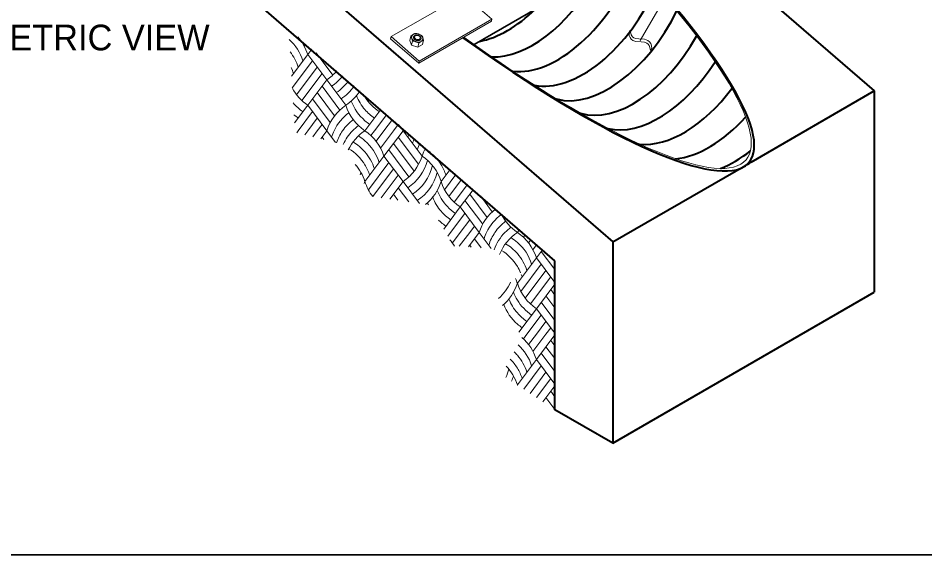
# Model space of a CAD drawing. Extents: x 99860 to 103153, y 99998 to 102077.
# Drawn here: x 101841 to 102547, y 100000 to 100418 of the extents above; entities that cross this region are included whole.
import ezdxf
from ezdxf.enums import TextEntityAlignment as Align

# ---------------------------------------------------------------- set-up
doc = ezdxf.new("R2010")
doc.units = 0
doc.header["$LTSCALE"] = 6.4
for name, color, linetype, lineweight in [('1', 7, 'Continuous', 13), ('15', 7, 'Continuous', 13), ('20', 7, 'Continuous', 13), ('30', 7, 'Continuous', 40), ('9', 7, 'Continuous', 13)]:
    doc.layers.add(name, color=color, linetype=linetype, lineweight=lineweight)

msp = doc.modelspace()

# ---------------------------------------------------------------- linework, layer by layer
at = {"layer": '1', "lineweight": 40}
for p, q in [((101553.775, 100893.223), (102304.358, 100243.197)), ((102259.104, 100228.525), (101542.799, 100848.864)), ((101988.262, 100810.884), (102508.005, 100360.773)), ((102412.037, 100305.365), (102508.005, 100360.773)), ((102508.005, 100360.773), (102508.005, 100204.005)), ((102304.358, 100243.197), (102400.327, 100298.604)), ((102304.358, 100243.197), (102304.358, 100086.43)), ((102304.358, 100086.43), (102508.005, 100204.005))]:
    msp.add_line(p, q, dxfattribs=at)
at = {"layer": '1', "lineweight": 35}
msp.add_line((102296.76, 100455.017), (102196.139, 100396.923), dxfattribs=at)
at = {"layer": '1'}
for p, q in [((102209.658, 100415.026), (102153.09, 100382.366)), ((102210.087, 100416.759), (102153.518, 100384.099)), ((102209.658, 100415.026), (102210.087, 100416.759)), ((102131.567, 100403.11), (102131.138, 100401.377)), ((102153.09, 100382.366), (102131.138, 100401.377)), ((102153.518, 100384.099), (102131.567, 100403.11)), ((102153.09, 100382.366), (102187.598, 100402.29)), ((102153.09, 100382.366), (102153.518, 100384.099))]:
    msp.add_line(p, q, dxfattribs=at)
at = {"layer": '1', "lineweight": 35}
msp.add_lwpolyline([(99862, 99999.5), (103151, 99999.5), (103151, 102075.5), (99862, 102075.5)], close=True, dxfattribs=at)
at = {"layer": '1'}
msp.add_lwpolyline([(102210.087, 100416.759), (102188.135, 100435.77), (102131.567, 100403.11)], dxfattribs=at)
at = {"layer": '1', "lineweight": 40}
msp.add_lwpolyline([(102304.358, 100086.43), (102259.104, 100112.558), (102259.104, 100228.525)], dxfattribs=at)
for centre, major_axis, ratio, start_param, end_param in [((102135.042, 100536.619), (275.44, -231.358), 0.205372, 5.0720591, 7.3453233), ((102406.182, 100380.076), (-48, -83.138), 0.57735, 0.6990402, 0.8717561)]:
    msp.add_ellipse(centre, major_axis=major_axis, ratio=ratio, start_param=start_param, end_param=end_param, dxfattribs=at)
at = {"layer": '1'}
msp.add_ellipse((102135.042, 100536.619), major_axis=(273.144, -229.43), ratio=0.205372, start_param=5.0759591, end_param=7.3414234, dxfattribs=at)
at = {"layer": '15'}
msp.add_line((102325.738, 100400.113), (102401.808, 100531.871), dxfattribs=at)
at = {"layer": '20'}
for p, q in [((102060.461, 100400.861), (102060.714, 100401.199)), ((102063.904, 100395.553), (102065.206, 100397.289)), ((102066.579, 100389.219), (102069.698, 100393.379)), ((102073.112, 100390.408), (102086.082, 100373.114)), ((102053.988, 100372.432), (102066.579, 100389.219)), ((102054.553, 100363.286), (102070.291, 100384.27)), ((102066.579, 100389.219), (102081.428, 100369.421)), ((102057.847, 100357.779), (102074.003, 100379.32)), ((102061.924, 100353.315), (102077.716, 100374.37)), ((102066.579, 100349.622), (102081.428, 100369.421)), ((102081.428, 100369.421), (102096.277, 100349.622)), ((102077.716, 100364.471), (102091.623, 100345.928)), ((102074.003, 100359.521), (102087.546, 100341.464)), ((102056.247, 100335.846), (102066.579, 100349.622)), ((102066.579, 100349.622), (102081.428, 100329.823)), ((102070.291, 100354.571), (102084.102, 100336.156)), ((102059.154, 100329.823), (102070.291, 100344.672)), ((102111.125, 100329.823), (102123.604, 100346.461)), ((102118.55, 100329.823), (102128.096, 100342.551)), ((102066.579, 100329.823), (102074.003, 100339.722)), ((102074.003, 100329.823), (102077.716, 100334.772)), ((102125.975, 100329.823), (102132.588, 100338.641)), ((102133.399, 100329.823), (102137.081, 100334.731)), ((102137.259, 100334.576), (102140.824, 100329.823)), ((102057.956, 100328.225), (102059.154, 100329.823)), ((102064.208, 100326.662), (102066.579, 100329.823)), ((102070.46, 100325.099), (102074.003, 100329.823)), ((102076.713, 100323.535), (102081.428, 100329.822)), ((102081.428, 100329.822), (102088.319, 100320.634)), ((102115.78, 100326.129), (102118.55, 100329.823)), ((102119.857, 100321.665), (102125.975, 100329.823)), ((102123.3, 100316.357), (102133.399, 100329.823)), ((102125.975, 100310.023), (102140.824, 100329.822)), ((102140.824, 100329.822), (102155.673, 100310.023)), ((102077.716, 100324.873), (102079.181, 100322.918)), ((102133.399, 100319.923), (102149.555, 100298.382)), ((102137.112, 100324.873), (102152.999, 100303.69)), ((102129.687, 100314.973), (102145.478, 100293.918)), ((102111.125, 100290.225), (102125.975, 100310.023)), ((102125.975, 100310.023), (102140.824, 100290.225)), ((102113.8, 100283.891), (102129.687, 100305.074)), ((102117.243, 100278.583), (102133.399, 100300.124)), ((102170.521, 100290.225), (102177.51, 100299.542)), ((102123.916, 100277.58), (102137.112, 100295.174)), ((102173.196, 100283.891), (102182.002, 100295.632)), ((102176.639, 100278.583), (102186.494, 100291.723)), ((102130.595, 100276.585), (102140.824, 100290.225)), ((102137.112, 100285.275), (102145.268, 100274.4)), ((102140.824, 100290.225), (102153.626, 100273.155)), ((102180.716, 100274.119), (102190.986, 100287.813)), ((102133.399, 100280.325), (102136.909, 100275.645)), ((102185.371, 100270.426), (102195.479, 100283.903)), ((102192.795, 100280.325), (102206.338, 100262.268)), ((102201.406, 100278.744), (102210.415, 100266.732)), ((102172.501, 100253.266), (102185.371, 100270.426)), ((102185.371, 100270.426), (102200.22, 100250.627)), ((102189.083, 100275.375), (102202.894, 100256.96)), ((102177.946, 100250.627), (102189.083, 100265.476)), ((102185.371, 100250.627), (102192.795, 100260.526)), ((102175.683, 100247.609), (102177.946, 100250.627)), ((102179.253, 100242.469), (102185.371, 100250.627)), ((102184.678, 100239.803), (102192.795, 100250.627)), ((102191.76, 100239.346), (102200.22, 100250.626)), ((102192.795, 100250.627), (102196.508, 100255.576)), ((102200.22, 100250.626), (102209.54, 100238.199)), ((102229.917, 100250.627), (102231.415, 100252.624)), ((102234.572, 100246.933), (102235.908, 100248.714)), ((102196.508, 100245.677), (102201.738, 100238.702)), ((102238.649, 100242.469), (102240.4, 100244.804)), ((102192.795, 100240.727), (102193.936, 100239.206)), ((102242.092, 100237.161), (102244.892, 100240.894)), ((102244.767, 100230.827), (102249.384, 100236.984)), ((102248.479, 100235.777), (102259.104, 100221.611)), ((102229.917, 100211.029), (102244.767, 100230.827)), ((102244.767, 100230.827), (102259.104, 100211.712)), ((102232.592, 100204.695), (102248.479, 100225.878)), ((102236.035, 100199.387), (102252.191, 100220.928)), ((102240.112, 100194.923), (102255.904, 100215.978)), ((102244.767, 100191.23), (102259.104, 100210.345)), ((102252.191, 100201.129), (102259.104, 100191.913)), ((102255.904, 100206.079), (102259.104, 100201.812)), ((102248.479, 100196.179), (102259.104, 100182.013)), ((102230.985, 100172.854), (102244.767, 100191.23)), ((102237.342, 100171.431), (102248.479, 100186.28)), ((102244.767, 100191.23), (102259.104, 100172.114)), ((102244.767, 100171.431), (102252.191, 100181.33)), ((102234.572, 100167.737), (102237.342, 100171.431)), ((102238.649, 100163.273), (102244.767, 100171.431)), ((102242.092, 100157.965), (102252.191, 100171.431)), ((102252.191, 100171.431), (102255.904, 100176.38)), ((102244.767, 100151.631), (102259.104, 100170.747)), ((102255.904, 100166.481), (102259.104, 100162.214)), ((102252.191, 100161.531), (102259.104, 100152.315)), ((102229.917, 100131.833), (102244.767, 100151.631)), ((102244.767, 100151.631), (102259.104, 100132.516)), ((102248.479, 100156.581), (102259.104, 100142.415)), ((102234.833, 100128.487), (102248.479, 100146.682)), ((102239.808, 100125.222), (102252.191, 100141.732)), ((102244.784, 100121.956), (102255.904, 100136.782)), ((102249.759, 100118.69), (102259.104, 100131.149)), ((102252.191, 100121.933), (102259.104, 100112.717)), ((102255.904, 100126.883), (102259.104, 100122.616))]:
    msp.add_line(p, q, dxfattribs=at)
msp.add_lwpolyline([(102319.597, 100403.062), (102318.725, 100404.459), (102317.742, 100408.022), (102316.685, 100406.191), (102317.046, 100404.075), (102317.691, 100402.417), (102318.648, 100401.115), (102319.974, 100400.111), (102322.272, 100399.217), (102326.354, 100398.953), (102328.895, 100398.727), (102330.708, 100398.095), (102331.757, 100397.273), (102332.563, 100396.176), (102333.183, 100394.555), (102333.7, 100392.186), (102334.757, 100394.016), (102334.502, 100395.989), (102333.869, 100397.665), (102332.852, 100399.035), (102331.453, 100400.106), (102328.896, 100401.035), (102324.5, 100401.408), (102322.085, 100401.612), (102320.681, 100402.143)], close=True, dxfattribs=at)
for centre, start, end in [((102030.769, 100377.83), 56.09546, 56.09634), ((102030.769, 100377.83), 56.09229, 56.09546), ((102027.056, 100372.88), 17.6434, 47.92144), ((102030.769, 100377.83), 17.6434, 41.83649), ((102023.344, 100367.931), 17.6434, 38.31474), ((102019.632, 100362.981), 17.6434, 25.40054), ((102060.467, 100400.609), 303.90361, 319.88998), ((102064.18, 100395.659), 303.90361, 321.8678), ((102087.539, 100380.81), 208.72411, 236.09639), ((102067.892, 100390.709), 303.90361, 323.8491), ((102071.604, 100385.76), 303.90361, 325.83627), ((102075.317, 100380.81), 303.90361, 327.83179), ((102139.512, 100370.91), 201.43438, 220.94161), ((102143.224, 100375.86), 207.86013, 211.33197), ((102143.223, 100375.86), 211.33188, 236.09639), ((102083.827, 100375.86), 220.57668, 236.09639), ((102117.238, 100318.433), 123.90361, 162.3566), ((102132.087, 100361.011), 197.6434, 236.09639), ((102135.799, 100365.961), 200.24322, 228.95992), ((102080.115, 100370.91), 229.78728, 236.09639), ((102120.95, 100313.483), 126.30626, 154.22661), ((102139.511, 100370.91), 220.94154, 236.09639), ((102124.662, 100308.534), 127.1006, 145.49109), ((102128.375, 100303.584), 126.331, 135.71278), ((102135.798, 100365.961), 228.95986, 236.09639), ((102120.95, 100313.483), 154.22654, 162.3566), ((102124.662, 100308.534), 145.49102, 161.50024), ((102128.375, 100303.584), 135.71269, 155.49774), ((102132.087, 100298.634), 123.90361, 154.373), ((102090.165, 100298.634), 17.6434, 56.09634), ((102176.634, 100318.433), 160.30383, 162.3566), ((102180.346, 100313.483), 158.19633, 162.3566), ((102082.741, 100288.735), 40.94134, 59.30215), ((102086.453, 100293.684), 48.95968, 58.54646), ((102086.452, 100293.684), 17.6434, 48.95974), ((102184.058, 100308.534), 156.1156, 162.3566), ((102187.771, 100303.584), 154.05795, 162.3566), ((102079.029, 100283.785), 31.33163, 58.48736), ((102082.74, 100288.735), 17.6434, 40.94141), ((102191.483, 100298.634), 152.02004, 162.3566), ((102138.425, 100283.785), 51.29644, 58.48736), ((102119.863, 100321.413), 303.90361, 342.3566), ((102123.576, 100316.463), 303.90361, 345.01126), ((102134.713, 100278.835), 17.6434, 56.09639), ((102138.425, 100283.785), 31.33163, 46.63234), ((102075.317, 100278.835), 17.6434, 41.28523), ((102067.892, 100311.513), 345.51092, 346.31988), ((102079.028, 100283.785), 17.6434, 31.33172), ((102127.288, 100311.513), 303.90361, 346.31988), ((102138.424, 100283.785), 17.6434, 31.33172), ((102071.604, 100306.564), 342.67112, 345.77134), ((102131, 100306.564), 303.90361, 345.77133), ((102075.317, 100301.614), 339.97622, 342.3566), ((102146.935, 100301.614), 197.64354, 217.81866), ((102134.713, 100301.614), 309.08024, 342.3566), ((102206.331, 100301.614), 197.64354, 236.09639), ((102198.908, 100291.714), 201.43438, 220.94161), ((102202.62, 100296.664), 200.87781, 211.33197), ((102202.619, 100296.664), 211.33188, 236.09639), ((102195.195, 100286.765), 200.24322, 202.94034), ((102198.907, 100291.714), 220.94154, 236.09639), ((102236.03, 100239.237), 128.12233, 162.3566), ((102239.742, 100234.287), 126.30626, 154.22661), ((102250.879, 100281.815), 206.78548, 236.09639), ((102195.195, 100286.765), 224.90332, 228.95992), ((102195.194, 100286.765), 228.95986, 236.09639), ((102243.454, 100229.338), 127.1006, 145.49109), ((102239.742, 100234.287), 154.22654, 162.3566), ((102243.454, 100229.338), 145.49102, 162.3566), ((102247.167, 100224.388), 135.71269, 160.14729), ((102250.879, 100219.438), 123.90361, 158.03778), ((102247.167, 100224.388), 126.331, 135.71278), ((102208.957, 100219.438), 17.6434, 56.09634), ((102149.561, 100219.438), 33.2494, 42.59671), ((102201.533, 100209.539), 40.94134, 59.30215), ((102205.245, 100214.488), 48.95968, 58.54646), ((102205.244, 100214.488), 17.6434, 48.95974), ((102197.821, 100204.589), 31.33163, 58.48736), ((102201.532, 100209.539), 17.6434, 40.94141), ((102197.82, 100204.589), 22.93575, 31.33172), ((102194.109, 100199.639), 17.6434, 23.58804), ((102197.82, 100204.589), 17.6434, 20.65552), ((102190.396, 100227.368), 311.32441, 335.66285), ((102194.109, 100222.418), 310.33908, 342.3566), ((102265.727, 100222.418), 197.64354, 236.09639), ((102262.016, 100217.468), 200.87781, 211.33197), ((102254.591, 100207.569), 200.24322, 228.95992), ((102258.304, 100212.518), 201.43438, 220.94161), ((102262.015, 100217.468), 211.33188, 236.09639), ((102258.303, 100212.518), 220.94154, 236.09639), ((102254.59, 100207.569), 228.95986, 236.09639), ((102208.957, 100140.242), 17.6434, 49.3061), ((102201.533, 100130.343), 40.94134, 46.36292), ((102205.244, 100135.292), 17.6434, 47.71239), ((102197.821, 100125.393), 31.33163, 45.00368), ((102201.532, 100130.343), 17.6434, 40.94141), ((102186.684, 100153.121), 335.63908, 346.31988), ((102194.109, 100120.443), 17.6434, 43.63506), ((102197.82, 100125.393), 17.6434, 31.33172), ((102190.396, 100148.172), 338.89824, 345.77133), ((102194.109, 100143.222), 342.19797, 342.3566), ((102265.727, 100143.222), 197.64354, 197.88516)]:
    msp.add_arc(centre, 37.577, start, end, dxfattribs=at)
at = {"layer": '30'}
for centre, start_param, end_param in [((102261.606, 100463.547), 0.2409972, 1.8618241), ((102241.947, 100474.897), 0.295282, 1.5815991), ((102281.264, 100452.197), 0.189709, 1.7776366), ((102222.288, 100486.247), 0.4582614, 1.112535), ((102300.923, 100440.847), 0.1470682, 1.6884568), ((102320.582, 100429.497), 0.1293655, 1.5924022), ((102340.241, 100418.147), 0.1634814, 1.4864035), ((102359.899, 100406.798), 0.2518862, 1.3647232), ((102379.558, 100395.448), 0.3873794, 1.2136899), ((102399.217, 100384.098), 0.6241253, 0.9685715)]:
    msp.add_ellipse(centre, major_axis=(-48, -83.138), ratio=0.57735, start_param=start_param, end_param=end_param, dxfattribs=at)
at = {"layer": '9'}
for p, q in [((102146.935, 100403.476), (102146.104, 100400.116)), ((102146.104, 100400.116), (102147.353, 100396.383)), ((102147.606, 100401.955), (102147.652, 100401.82)), ((102150.599, 100399.253), (102150.832, 100399.177)), ((102153.108, 100398.131), (102152.277, 100394.77)), ((102154.935, 100399.424), (102155.092, 100399.514)), ((102156.782, 100400.252), (102155.95, 100396.891)), ((102152.277, 100394.77), (102155.95, 100396.891))]:
    msp.add_line(p, q, dxfattribs=at)
msp.add_lwpolyline([(102148.185, 100399.743), (102147.353, 100396.383), (102152.277, 100394.77)], dxfattribs=at)
for major_axis, start_param, end_param in [((4.368, -1.081), 2.5125792, 3.5388869), ((4.368, -1.081), 0.431368, 2.5125792), ((4.368, -1.081), 3.5806665, 4.5797326), ((-2.912, 0.721), 5.6541718, 6.7144408), ((4.368, -1.081), 4.634216, 5.6294447), ((4.368, -1.081), 5.678899, 6.68814)]:
    msp.add_ellipse((102151.927, 100402.142), major_axis=major_axis, ratio=0.700141, start_param=start_param, end_param=end_param, dxfattribs=at)
msp.add_ellipse((102151.995, 100402.428), major_axis=(2.213, -0.548), ratio=0.700141, dxfattribs=at)
for points in [[(102146.935, 100403.476), (102147.087, 100403.598), (102147.239, 100403.718), (102147.391, 100403.834), (102147.877, 100404.205), (102148.368, 100404.542), (102148.84, 100404.815)], [(102148.84, 100404.815), (102148.998, 100404.906), (102149.153, 100404.99), (102149.307, 100405.068), (102149.76, 100405.296), (102150.194, 100405.466), (102150.609, 100405.597)], [(102154.877, 100401.911), (102154.897, 100401.671), (102154.861, 100401.431), (102154.771, 100401.213), (102154.681, 100400.994), (102154.535, 100400.791), (102154.345, 100400.619), (102154.155, 100400.448), (102153.915, 100400.303), (102153.646, 100400.198), (102153.377, 100400.092), (102153.071, 100400.023), (102152.753, 100399.995), (102152.436, 100399.968), (102152.098, 100399.981), (102151.768, 100400.035), (102151.437, 100400.088), (102151.106, 100400.183), (102150.8, 100400.312), (102150.494, 100400.441), (102150.206, 100400.606), (102149.959, 100400.796), (102149.713, 100400.985), (102149.5, 100401.203), (102149.341, 100401.431), (102149.181, 100401.659), (102149.069, 100401.905), (102149.013, 100402.147), (102148.958, 100402.389), (102148.959, 100402.634), (102149.015, 100402.862), (102149.071, 100403.09), (102149.184, 100403.307), (102149.345, 100403.496), (102149.506, 100403.684), (102149.718, 100403.849), (102149.966, 100403.977), (102150.213, 100404.105), (102150.502, 100404.199), (102150.808, 100404.252), (102151.114, 100404.304), (102151.446, 100404.317), (102151.776, 100404.289), (102152.107, 100404.26), (102152.444, 100404.19), (102152.762, 100404.083), (102153.079, 100403.977), (102153.385, 100403.832), (102153.653, 100403.659), (102153.922, 100403.487), (102154.16, 100403.283), (102154.35, 100403.064), (102154.539, 100402.845), (102154.685, 100402.606), (102154.774, 100402.365), (102154.829, 100402.215), (102154.864, 100402.062), (102154.877, 100401.911)], [(102155.532, 100403.985), (102154.725, 100404.444), (102153.858, 100404.849), (102152.968, 100405.124), (102152.191, 100405.364), (102151.391, 100405.511), (102150.609, 100405.597)], [(102146.935, 100403.476), (102147.171, 100403.055), (102147.401, 100402.555), (102147.606, 100401.955)], [(102147.652, 100401.82), (102147.658, 100401.799), (102147.665, 100401.778), (102147.672, 100401.758), (102147.865, 100401.158), (102148.035, 100400.464), (102148.185, 100399.743)], [(102148.185, 100399.743), (102148.986, 100399.655), (102149.805, 100399.503), (102150.599, 100399.253)], [(102150.832, 100399.177), (102150.85, 100399.171), (102150.868, 100399.165), (102150.885, 100399.159), (102151.656, 100398.892), (102152.403, 100398.532), (102153.108, 100398.131)], [(102153.108, 100398.131), (102153.26, 100398.253), (102153.412, 100398.372), (102153.564, 100398.488), (102154.023, 100398.839), (102154.486, 100399.159), (102154.935, 100399.424)], [(102155.092, 100399.514), (102155.222, 100399.588), (102155.352, 100399.657), (102155.48, 100399.722), (102155.932, 100399.95), (102156.367, 100400.12), (102156.782, 100400.252)], [(102156.212, 100402.439), (102156.202, 100402.468), (102156.192, 100402.496), (102156.182, 100402.525), (102155.982, 100403.098), (102155.76, 100403.578), (102155.532, 100403.985)], [(102156.782, 100400.252), (102156.625, 100401.007), (102156.445, 100401.733), (102156.24, 100402.353)]]:
    msp.add_open_spline(points, degree=3, dxfattribs=at)

# ---------------------------------------------------------------- texts
at = {"layer": '20'}
msp.add_text('ISOMETRIC VIEW', height=20, dxfattribs=at).set_placement((101877.944, 100392.411), align=Align.CENTER)

doc.saveas('drawing.dxf')
